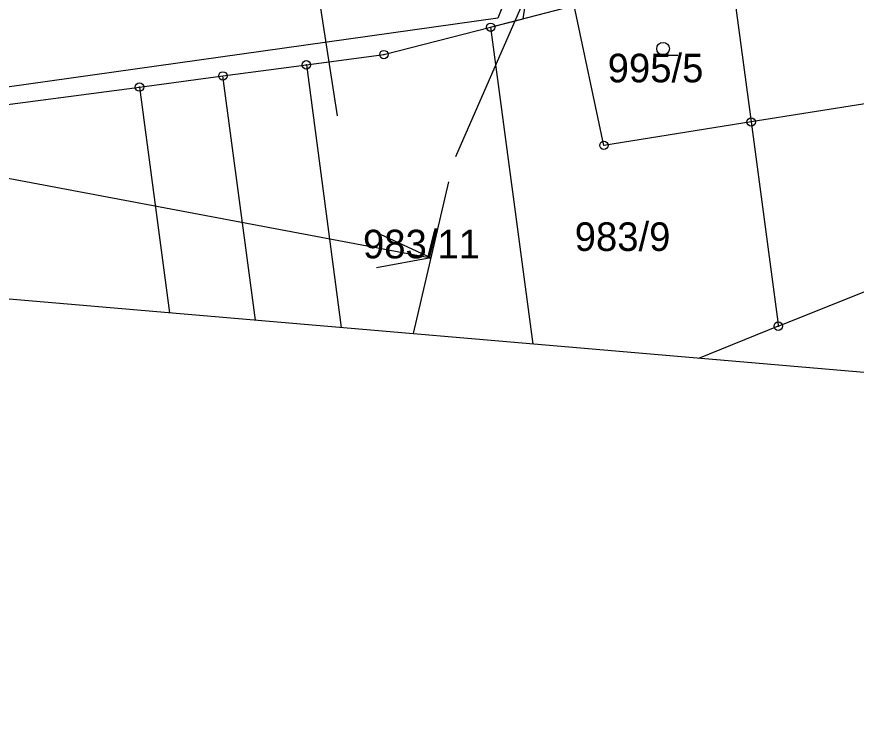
# Model space of a CAD drawing. Extents: x -537341 to -532984, y -1143469 to -1141314.
# Drawn here: x -533721.2 to -533621.4, y -1143459.1 to -1143376 of the extents above; entities that cross this region are included whole.
import ezdxf

# ---------------------------------------------------------------- set-up
doc = ezdxf.new("R2010")
doc.units = 0
for name, color, linetype in [('Hranice parcel', 7, 'Continuous'), ('parcelní_č_2000', 7, 'Continuous'), ('u_nadpis', 7, 'Continuous'), ('u_povodí', 7, 'Continuous'), ('u_pricne', 7, 'Continuous'), ('Věcná břemena k části', 7, 'Continuous'), ('x_formát_rám', 7, 'Continuous'), ('Značky bodu BP', 7, 'Continuous'), ('Značky kultur', 7, 'Continuous')]:
    doc.layers.add(name, color=color, linetype=linetype)

# ---------------------------------------------------------------- blocks, each defined once
blk = doc.blocks.new('BIG')
at = {"layer": 'x_formát_rám'}
blk.add_line((0, 0), (-2100, 0), dxfattribs=at)

msp = doc.modelspace()

# ---------------------------------------------------------------- linework, layer by layer
at = {"layer": 'Hranice parcel'}
for p, q in [((-533664.85, -1143377.25), (-533654.92, -1143374.67)), ((-533664.85, -1143377.25), (-533659.844, -1143414.945)), ((-533696.67, -1143383.04), (-533686.76, -1143381.72)), ((-533686.76, -1143381.72), (-533682.606, -1143412.987)), ((-533706.59, -1143384.36), (-533696.67, -1143383.04)), ((-533692.807, -1143412.11), (-533696.67, -1143383.04)), ((-533724.44, -1143386.73), (-533706.59, -1143384.36)), ((-533706.59, -1143384.36), (-533703.019, -1143411.231)), ((-533630.66, -1143412.81), (-533640.155, -1143416.639))]:
    msp.add_line(p, q, dxfattribs=at)
for points in [[(-533636.43, -1143369.53), (-533635.69, -1143374.94), (-533633.89, -1143388.52)], [(-533633.89, -1143388.52), (-533651.39, -1143391.3), (-533654.92, -1143374.67)], [(-533686.76, -1143381.72), (-533677.54, -1143380.5), (-533664.85, -1143377.25)], [(-533561.095, -1143376.879), (-533598.82, -1143382.95), (-533633.89, -1143388.52)], [(-533630.66, -1143412.81), (-533561.818, -1143385.281)], [(-533633.89, -1143388.52), (-533630.73, -1143412.31), (-533630.66, -1143412.81)]]:
    msp.add_lwpolyline(points, dxfattribs=at)
at = {"layer": 'u_nadpis'}
for p, q in [((-533669.875, -1143395.646), (-533674.064, -1143413.687)), ((-533671.969, -1143404.666), (-533677.946, -1143401.897)), ((-533671.969, -1143404.666), (-533678.421, -1143405.873))]:
    msp.add_line(p, q, dxfattribs=at)
msp.add_lwpolyline([(-535757.21, -1143234.504), (-535708.696, -1143186.182), (-535532.302, -1143063.527), (-535234.92, -1142978.146), (-534703.861, -1143121.984), (-534494.708, -1143163.575), (-534139.733, -1143316.613), (-533671.969, -1143404.666)], dxfattribs=at)
at = {"layer": 'u_pricne'}
for p, q in [((-533703.84, -1143254.13), (-533683.097, -1143387.777)), ((-533614.281, -1143267.159), (-533669.037, -1143392.684))]:
    msp.add_line(p, q, dxfattribs=at)
at = {"layer": 'Věcná břemena k části'}
msp.add_lwpolyline([(-533686.76, -1143381.72), (-533677.54, -1143380.5), (-533664.85, -1143377.25), (-533661, -1143376.25), (-533659.14, -1143364.21), (-533658.92, -1143362.7), (-533661.89, -1143362.24), (-533662.52, -1143366.39), (-533662.83, -1143373.26), (-533664, -1143376.17), (-533767.99, -1143390.79), (-533755.18, -1143390.81), (-533724.44, -1143386.73), (-533706.59, -1143384.36), (-533696.67, -1143383.04)], close=True, dxfattribs=at)
at = {"layer": 'Značky bodu BP'}
for centre, radius in [((-533664.85, -1143377.25), 0.5), ((-533664.85, -1143377.25), 0.0303), ((-533677.54, -1143380.5), 0.5), ((-533677.54, -1143380.5), 0.0303), ((-533686.76, -1143381.72), 0.5), ((-533686.76, -1143381.72), 0.0303), ((-533696.67, -1143383.04), 0.5), ((-533696.67, -1143383.04), 0.0303), ((-533706.59, -1143384.36), 0.5), ((-533706.59, -1143384.36), 0.0303), ((-533633.89, -1143388.52), 0.5), ((-533633.89, -1143388.52), 0.0303), ((-533651.39, -1143391.3), 0.5), ((-533651.39, -1143391.3), 0.0303), ((-533630.66, -1143412.81), 0.5), ((-533630.66, -1143412.81), 0.0303)]:
    msp.add_circle(centre, radius, dxfattribs=at)
at = {"layer": 'Značky kultur'}
msp.add_line((-533644.353, -1143380.56), (-533642.603, -1143380.56), dxfattribs=at)
msp.add_circle((-533644.353, -1143379.81), 0.75, dxfattribs=at)

# ---------------------------------------------------------------- block references
at = {"layer": 'u_povodí', "xscale": 2.0000000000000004, "yscale": 1.9999999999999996, "rotation": -4.9171773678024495}
msp.add_blockref('BIG', (-533146.617, -1143459.1), dxfattribs=at)

# ---------------------------------------------------------------- texts
at = {"layer": 'parcelní_č_2000'}
for s, p in [('995/5', (-533650.94, -1143383.8)), ('983/9', (-533654.86, -1143403.86)), ('983/11', (-533680.025, -1143404.74))]:
    msp.add_text(s, height=3.4, dxfattribs=at).set_placement(p)

doc.saveas('drawing.dxf')
